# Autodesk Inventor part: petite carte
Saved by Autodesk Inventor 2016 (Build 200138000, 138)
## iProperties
Created: 2013-10
Part Number: petite carte
Material: Générique
Document SubType Name: Modeling
Designer: Bruno
Density: 1 g/cm^3
Appearance: Par défaut
Author: Bruno
Sending System: SolidWorks 2013
Last Author: christophe
Last Saved: 2014-02-15
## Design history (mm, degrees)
feature "Boss.-Extru.3"
node "Solide1"
